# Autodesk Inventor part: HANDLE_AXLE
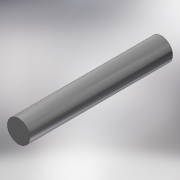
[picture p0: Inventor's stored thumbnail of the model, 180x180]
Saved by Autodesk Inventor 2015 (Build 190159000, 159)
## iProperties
Created: 2014-08
Part Number: HANDLE_AXLE
Material: Steel, Mild
Document SubType Name: Modeling
Designer: lakshayg
Density: 7.85 g/cm^3
Appearance: Semi-Polished
Mass: 67.6514 g
Surface Area: 30.9887 cm^2
Volume: 8.61802 cm^3
Author: lakshayg
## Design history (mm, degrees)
sketch "Sketch1"
  geometry: C1 r 6 at (0, 0); 1 further point
  constraints: 1 centre point, 1 coincident
  dimensions: "d0" = 12 diameter of C1
extrude "Extrusion1" new body sketch "Sketch1" distance "d1" = 76.2; taper "d2" = 0 deg
body "Solid1"
